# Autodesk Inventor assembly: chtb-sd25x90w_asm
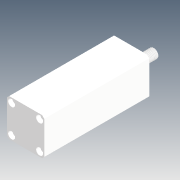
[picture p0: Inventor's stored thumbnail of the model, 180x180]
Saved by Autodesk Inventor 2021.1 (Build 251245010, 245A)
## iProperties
Company: Microsoft
Created: 2018-05
Part Number: chtb-sd25x90w_asm
Description: STEP AP214
Document SubType Name: Assembly
Designer: user
Title: chtb-sd25x90w_asm.STEP
Author: Windows
Revision Number: ÈÎºÎ
Sending System: SolidWorks 2015
Preprocessor: SwSTEP 2.0
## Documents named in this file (4)
- D:\Vault_2016\Projekty\Clamptek\Hydraulic\CHTB\CHTB-25\Inventor\chtb-sd25x90w\chtb-sd25x90w_asm.iam
- D:\Vault_2016\Projekty\Clamptek\Hydraulic\CHTB\CHTB-25\Inventor\chtb-sd25x90w\CHTB-25QG.ipt
- D:\Vault_2016\Projekty\Clamptek\Hydraulic\CHTB\CHTB-25\Inventor\chtb-sd25x90w\CHTB-SD25X90NBT.ipt
- D:\Vault_2016\Projekty\Clamptek\Hydraulic\CHTB\CHTB-25\Inventor\chtb-sd25x90w\CHTB-SD25X90WHSG.ipt
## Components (3 placed, 3 different names)
1. CHTB-25QG_1
2. CHTB-SD25X90NBT_2
3. CHTB-SD25X90WHSG_3
